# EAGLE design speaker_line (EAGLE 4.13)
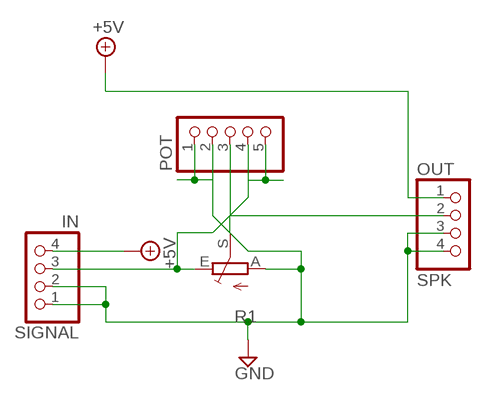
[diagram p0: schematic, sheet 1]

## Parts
OUT  SPK  PINHD-1X4  [1X04]
POT  PINHD-1X5  [1X05]
R1  TRIM_EU-PT10  [PT-10]
SIGNAL  IN  PINHD-1X4  [1X04]

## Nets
+5V: OUT.1 SIGNAL.4
GND: OUT.3 OUT.4 POT.1 POT.2 R1.A SIGNAL.1 SIGNAL.2
N$1: OUT.2 POT.3 R1.S
N$2: POT.4 POT.5 R1.E SIGNAL.3

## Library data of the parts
OUT SIGNAL = pinhead:PINHD-1X4: PIN HEADER
POT = pinhead:PINHD-1X5: PIN HEADER
R1 = pot:TRIM_EU-: POTENTIOMETER

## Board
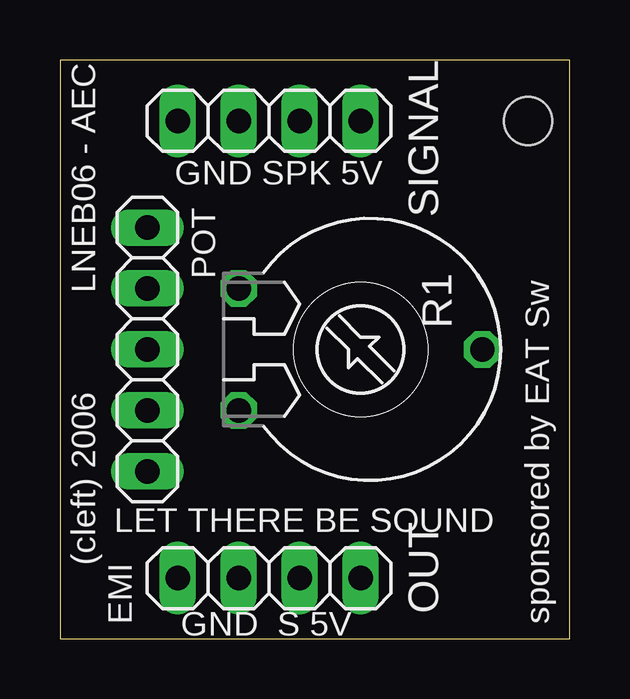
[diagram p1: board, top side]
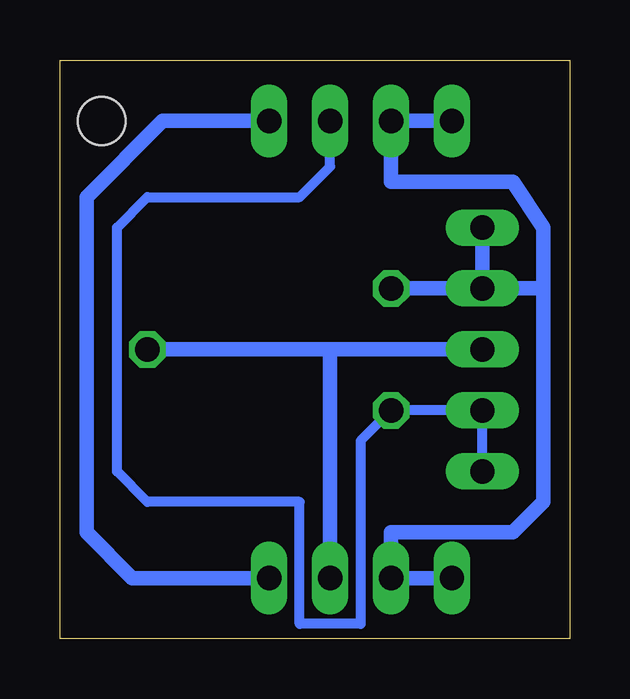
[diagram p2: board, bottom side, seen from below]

Size 21.26 x 24.12 mm. Coordinates in mm from the lower left corner, seen from the top.
Outline: 0,0 21.26,0 21.26,24.12 0,24.12 0,0
Copper layers (1*16): Top 0.035mm / dielectric 1.5mm / Bottom 0.035mm
Design rules "default": minimum track width 10mil, minimum drill 24mil, track to track 8mil, track to pad 8mil, pad to pad 8mil, via to via 8mil, smd to smd 8mil, copper to edge 40mil, drill to drill 8mil, minimum pad ring 10mil, minimum via ring 8mil, stop-mask expansion 4mil, vias tented up to drill 0mil, thermal gap 10mil
Holes 2 mm at 19.52,21.58

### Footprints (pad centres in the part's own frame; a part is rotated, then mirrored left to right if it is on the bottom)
1X04 = drill 1.016 long: 1 -3.81,0; 2 -1.27,0; 3 1.27,0; 4 3.81,0
1X05 = drill 1.016 long: 1 -5.08,0; 2 -2.54,0; 3 0,0; 4 2.54,0; 5 5.08,0
PT-10 = drill 1.016 octagon: A -2.54,-5.08; E 2.54,-5.08; S 0,5.08

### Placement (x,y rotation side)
OUT  8.73,2.54 180 top
POT  3.64,12.06 270 top
R1  12.54,12.06 270 top
SIGNAL  8.73,21.58 0 top

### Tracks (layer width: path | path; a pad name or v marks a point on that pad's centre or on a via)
+5V
  Bottom 0.61: SIGNAL.4 16.98,21.58 20.15,18.41 20.15,4.44 18.25,2.54 OUT.1
GND
  Bottom 0.406: OUT.3 7.46,3.17 | R1.A POT.2
  Bottom 0.61: POT.2 POT.1 | OUT.4 OUT.3 7.46,4.44 2.38,4.44 1.1,5.71 1.1,14.6 | 1.1,14.6 1.1,17.14 2.38,19.04 7.46,19.04 SIGNAL.2 SIGNAL.1 | 1.1,14.6 R1.A
N$1
  Bottom 0.61: OUT.2 10,12.06 | 10,12.06 POT.3 | 10,12.06 R1.S
N$2
  Bottom 0.406: POT.5 POT.4 R1.E 8.73,8.25 8.73,0.63 11.27,0.63 11.27,5.71 17.61,5.71 18.88,6.98 18.88,17.14 17.61,18.41 11.27,18.41 10,19.68 SIGNAL.3

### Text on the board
tPlace: LNEB06 - AEC | GND SPK 5V | (cleft) 2006 | LET THERE BE SOUND | EMI | sponsored by EAT Sw | GND S 5V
